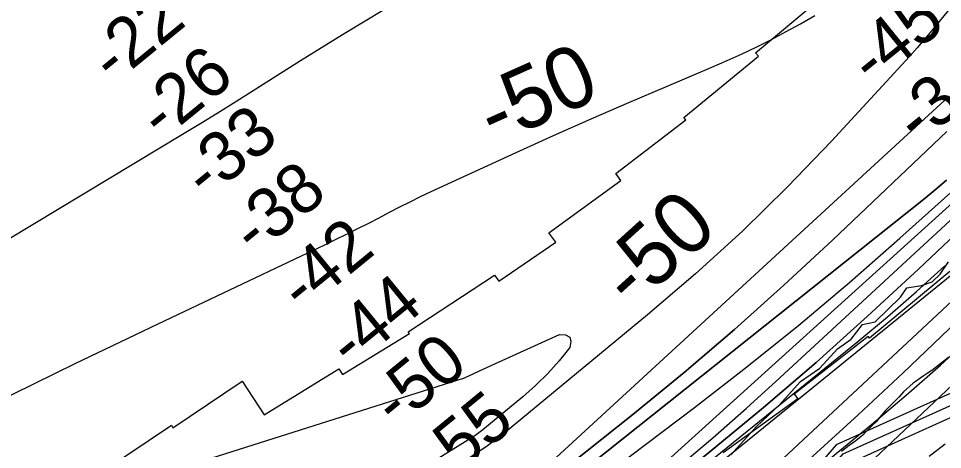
# Model space of a CAD drawing. Extents: x 3208593 to 3246461, y 812903 to 838290.
# Drawn here: x 3213280 to 3214527, y 829398 to 829979 of the extents above; entities that cross this region are included whole.
import ezdxf

# ---------------------------------------------------------------- set-up
doc = ezdxf.new("R2010")
doc.units = 0
for name, color, linetype in [('V-RIVR-EDGE', 7, 'Continuous'), ('V-RIVR-RANG', 7, 'Continuous'), ('V-ROAD-CNTR', 7, 'Continuous'), ('V-RRAP-RVMT', 7, 'Continuous'), ('V-SITE-VEGE', 7, 'Continuous'), ('V-TOPO-DPTH', 7, 'Continuous'), ('V-TOPO-MAJR', 7, 'Continuous'), ('V-TOPO-MAJR-IDEN', 7, 'Continuous'), ('V-TOPO-MINR', 7, 'Continuous'), ('V-TOPO-WATR', 7, 'Continuous')]:
    doc.layers.add(name, color=color, linetype=linetype)

msp = doc.modelspace()

# ---------------------------------------------------------------- linework, layer by layer
at = {"layer": 'V-RIVR-EDGE'}
msp.add_lwpolyline([(3214241.3, 829390.9), (3214276.1, 829428.7), (3214306.6, 829457.7), (3214335.4, 829489.4), (3214361.5, 829507.6), (3214385.5, 829533.6), (3214403.8, 829546.6), (3214419, 829566.5), (3214436, 829570), (3214470.4, 829603.4), (3214478.7, 829615.9), (3214498.7, 829618.9), (3214513.1, 829624.1), (3214524, 829634.1), (3214535.3, 829651)], dxfattribs=at)
at = {"layer": 'V-ROAD-CNTR'}
for points in [[(3212784, 828348.9), (3213009.9, 828462.9), (3213347.7, 828626.5), (3213606.3, 828811.3), (3213843.8, 828911.5), (3214091.9, 829054.1), (3214266.1, 829244.1), (3214392.8, 829391.9), (3214603.9, 829486.9), (3214720, 829566), (3214888.9, 829798.3), (3215094.8, 830091.2), (3215195, 830220.5), (3215374.5, 830389.5), (3215564.5, 830526.7), (3215728.1, 830700.9), (3215823.2, 830758.9), (3216097.6, 830838.1), (3216319.3, 830914.6)], [(3216324, 830900.4), (3216102.1, 830823.8), (3215829.2, 830745.1), (3215737.7, 830689.1), (3215574.5, 830515.4), (3215384.1, 830377.9), (3215206.2, 830210.4), (3215106.8, 830082.3), (3214901.1, 829789.6), (3214730.6, 829555.1), (3214611.2, 829473.7), (3214402, 829379.6), (3214277.3, 829234.1), (3214101.4, 829042.2), (3213850.5, 828898.1), (3213613.7, 828798.1), (3213355.3, 828613.6), (3213016.5, 828449.5), (3212783.7, 828331.9)], [(3214954.5, 829917.7), (3214876.7, 829807), (3214709.4, 829577), (3214596.5, 829500), (3214383.5, 829404.2), (3214254.8, 829254), (3214082.4, 829065.9), (3213837.1, 828925), (3213598.9, 828824.4), (3213340, 828639.5), (3213003.2, 828476.3), (3212784.3, 828365.8)]]:
    msp.add_lwpolyline(points, dxfattribs=at)
at = {"layer": 'V-RRAP-RVMT'}
for p, q in [((3214274.7, 829932.9), (3214365.8, 830008.8)), ((3214177.9, 829845.3), (3214278.6, 829928.2)), ((3214278.6, 829928.2), (3214274.7, 829932.9)), ((3214086.2, 829769.8), (3214180.6, 829842.3)), ((3214180.6, 829842.3), (3214177.9, 829845.3)), ((3213995.8, 829690.2), (3214093, 829760.6)), ((3214093, 829760.6), (3214086.2, 829769.8)), ((3214005.2, 829677.3), (3213995.8, 829690.2)), ((3213928.6, 829624.7), (3214005.2, 829677.3)), ((3214537, 829638.1), (3214428.7, 829548.1)), ((3213805.9, 829556.4), (3213922.7, 829632.9)), ((3213922.7, 829632.9), (3213928.6, 829624.7)), ((3213717.5, 829499.1), (3213807.7, 829554.1)), ((3213807.7, 829554.1), (3213805.9, 829556.4)), ((3214426.8, 829550.4), (3214327, 829472.3)), ((3214428.7, 829548.1), (3214426.8, 829550.4)), ((3213611.7, 829444.5), (3213712.6, 829506.8)), ((3213712.6, 829506.8), (3213717.5, 829499.1)), ((3213488.5, 829427.3), (3213581.9, 829490)), ((3213581.9, 829490), (3213611.7, 829444.5)), ((3214331.7, 829466.4), (3214231.1, 829393.5)), ((3214327, 829472.3), (3214331.7, 829466.4)), ((3213390.7, 829366.4), (3213486.5, 829430.5)), ((3213486.5, 829430.5), (3213488.5, 829427.3))]:
    msp.add_line(p, q, dxfattribs=at)
at = {"layer": 'V-SITE-VEGE'}
for p, q in [((3214523.1, 829512.3), (3214519.1, 829509.5)), ((3214534.9, 829521.9), (3214523.1, 829512.3)), ((3214506.2, 829500.5), (3214501, 829496.9)), ((3214513.8, 829505.5), (3214506.2, 829500.5)), ((3214519.1, 829509.5), (3214513.8, 829505.5)), ((3214487.6, 829487.1), (3214474.2, 829475.6)), ((3214490.2, 829489.1), (3214487.6, 829487.1)), ((3214497.8, 829494.5), (3214490.2, 829489.1)), ((3214501, 829496.9), (3214497.8, 829494.5)), ((3214474.2, 829475.6), (3214468.5, 829468.8)), ((3214468.5, 829468.8), (3214453.1, 829453.4)), ((3214450.3, 829450.4), (3214445.1, 829444.4)), ((3214453.1, 829453.4), (3214450.3, 829450.4)), ((3214437.6, 829435.4), (3214433.2, 829431.2)), ((3214442.3, 829441.4), (3214437.6, 829435.4)), ((3214445.1, 829444.4), (3214442.3, 829441.4)), ((3214426, 829423.8), (3214423.2, 829421.2)), ((3214433.2, 829431.2), (3214426, 829423.8)), ((3214415.2, 829413.4), (3214410, 829409.6)), ((3214419.4, 829417), (3214415.2, 829413.4)), ((3214423.2, 829421.2), (3214419.4, 829417)), ((3214400.9, 829403.3), (3214390.7, 829395.1)), ((3214410, 829409.6), (3214400.9, 829403.3)), ((3214509.2, 829388.9), (3214530.6, 829405.5))]:
    msp.add_line(p, q, dxfattribs=at)
at = {"layer": 'V-TOPO-DPTH'}
for points in [[(3212788.6, 829619.4), (3212788.2, 829398.7), (3212853, 829435.2), (3212924.1, 829476.5), (3212995, 829518.4), (3213504, 829824.3), (3213526.1, 829837.7), (3213548.2, 829851.2), (3213570.1, 829864.9), (3213592, 829878.6), (3213660.8, 829922.3), (3213717.3, 829957.4), (3213774.3, 829991.8)], [(3212788.2, 829398.7), (3212853, 829435.2), (3212924.1, 829476.5), (3212995, 829518.4), (3213504, 829824.3), (3213526.1, 829837.7), (3213548.2, 829851.2), (3213570.1, 829864.9), (3213592, 829878.6), (3213660.8, 829922.3), (3213717.3, 829957.4), (3213774.3, 829991.8)], [(3214535.8, 829874.5), (3213994.4, 829376.8), (3213988.6, 829371.6), (3213982.8, 829366.4), (3213976.8, 829361.4), (3213970.7, 829356.5), (3213959.8, 829347.8), (3213959.2, 829347.2), (3213957.8, 829346.3), (3213957.1, 829345.8), (3213945.8, 829339), (3213939.4, 829335.2), (3213933, 829331.4), (3213926.5, 829327.8), (3213920, 829324.3), (3213904, 829315.8), (3213889.5, 829308), (3213875, 829300.3), (3213860.4, 829292.5), (3213845.9, 829284.7), (3213307, 828996.7), (3213230.6, 828955.6)], [(3214535.8, 829874.5), (3213994.4, 829376.8), (3213988.6, 829371.6), (3213982.8, 829366.4), (3213976.8, 829361.4), (3213970.7, 829356.5), (3213959.8, 829347.8), (3213959.2, 829347.2), (3213957.8, 829346.3), (3213957.1, 829345.8), (3213945.8, 829339), (3213939.4, 829335.2), (3213933, 829331.4), (3213926.5, 829327.8), (3213920, 829324.3), (3213904, 829315.8), (3213889.5, 829308), (3213875, 829300.3), (3213860.4, 829292.5), (3213845.9, 829284.7), (3213307, 828996.7), (3213230.6, 828955.6)], [(3214532.8, 829826.7), (3214378.7, 829680.1), (3214313.1, 829619.3), (3214246.5, 829559.6), (3214178.3, 829501.8), (3214109.2, 829445.1), (3213983.9, 829345.2), (3213976.5, 829339.5), (3213968.9, 829334), (3213961.2, 829328.7), (3213953.3, 829323.7), (3213828.4, 829247.8), (3213757.6, 829205.5), (3213686.4, 829164), (3213614.6, 829123.7), (3213542.3, 829084), (3213000.4, 828792.6)], [(3213000.4, 828792.6), (3213542.3, 829084), (3213614.6, 829123.7), (3213686.4, 829164), (3213757.6, 829205.5), (3213828.4, 829247.8), (3213953.3, 829323.7), (3213961.2, 829328.7), (3213968.9, 829334), (3213976.5, 829339.5), (3213983.9, 829345.2), (3214109.2, 829445.1), (3214178.3, 829501.8), (3214246.5, 829559.6), (3214313.1, 829619.3), (3214378.7, 829680.1), (3214532.8, 829826.7)], [(3213207.6, 828830.7), (3213285.5, 828872.8), (3213363.5, 828914.6), (3213837, 829166.3), (3213860, 829178.5), (3213883, 829190.7), (3213906, 829202.8), (3213929.1, 829215), (3213950.6, 829226.3), (3213962.9, 829232.9), (3213975, 829239.6), (3213987, 829246.4), (3213999, 829253.5), (3214019.8, 829265.9), (3214021.2, 829266.9), (3214022.7, 829267.8), (3214025.5, 829269.9), (3214047.1, 829287.3), (3214059.3, 829297.2), (3214071.3, 829307.3), (3214083.1, 829317.5), (3214094.8, 829327.9), (3214597.3, 829781.5)], [(3213207.6, 828830.7), (3213285.5, 828872.8), (3213363.5, 828914.6), (3213837, 829166.3), (3213860, 829178.5), (3213883, 829190.7), (3213906, 829202.8), (3213929.1, 829215), (3213950.6, 829226.3), (3213962.9, 829232.9), (3213975, 829239.6), (3213987, 829246.4), (3213999, 829253.5), (3214019.8, 829265.9), (3214021.2, 829266.9), (3214022.7, 829267.8), (3214025.5, 829269.9), (3214047.1, 829287.3), (3214059.3, 829297.2), (3214071.3, 829307.3), (3214083.1, 829317.5), (3214094.8, 829327.9), (3214597.3, 829781.5)], [(3214532.6, 829761), (3214517.2, 829747.8), (3214501.5, 829734.8), (3214008.1, 829342.5), (3213993.9, 829331.7), (3213979.4, 829321.2), (3213964.5, 829311.2), (3213949.4, 829301.6), (3213712.7, 829157.8), (3213578.6, 829077.4), (3213443.9, 828997.9), (3213308.3, 828920), (3213172.1, 828843.1), (3212938, 828712.6), (3212911.6, 828697.6), (3212885.3, 828682.3), (3212859.2, 828666.7), (3212833.3, 828650.7), (3212786.7, 828621.7)], [(3212786.8, 828670.8), (3212786.7, 828621.7), (3212833.3, 828650.7), (3212859.2, 828666.7), (3212885.3, 828682.3), (3212911.6, 828697.6), (3212938, 828712.6), (3213172.1, 828843.1), (3213308.3, 828920), (3213443.9, 828997.9), (3213578.6, 829077.4), (3213712.7, 829157.8), (3213949.4, 829301.6), (3213964.5, 829311.2), (3213979.4, 829321.2), (3213993.9, 829331.7), (3214008.1, 829342.5), (3214501.5, 829734.8), (3214517.2, 829747.8), (3214532.6, 829761)], [(3214594.5, 829735.5), (3214494.5, 829640.9), (3214426, 829577.5), (3214356.5, 829515.3), (3214285.5, 829454.7), (3214213.6, 829395.2), (3214054.7, 829266.9), (3214045.1, 829259.5), (3214035.3, 829252.3), (3214025.3, 829245.6), (3214015.1, 829239.2), (3213870.5, 829152.5), (3213787.4, 829103.7), (3213703.8, 829055.9), (3213619.4, 829009.5), (3213534.4, 828964.2), (3213163.5, 828770.4)], [(3214594.5, 829735.5), (3214494.5, 829640.9), (3214426, 829577.5), (3214356.5, 829515.3), (3214285.5, 829454.7), (3214213.6, 829395.2), (3214054.7, 829266.9), (3214045.1, 829259.5), (3214035.3, 829252.3), (3214025.3, 829245.6), (3214015.1, 829239.2), (3213870.5, 829152.5), (3213787.4, 829103.7), (3213703.8, 829055.9), (3213619.4, 829009.5), (3213534.4, 828964.2), (3213163.5, 828770.4)], [(3212786.6, 828551.6), (3212786.4, 828493.6), (3212889, 828559.9), (3212912.2, 828574.5), (3212935.5, 828588.9), (3212959.2, 828602.8), (3212983.1, 828616.4), (3213186.2, 828729.4), (3213311.4, 828799.8), (3213436.2, 828871.1), (3213560.2, 828943.5), (3213683.8, 829016.8), (3214010.4, 829212.5), (3214029.4, 829224.4), (3214048, 829236.9), (3214066.1, 829250.1), (3214083.8, 829263.9), (3214604.5, 829686.5)]]:
    msp.add_lwpolyline(points, dxfattribs=at)
at = {"layer": 'V-TOPO-MAJR'}
for points in [[(3214568.4, 830031.2), (3214512.7, 829963), (3214502.8, 829951.2), (3214492.8, 829939.5), (3214482.6, 829927.9), (3214472.3, 829916.5), (3214377.1, 829813.6), (3214317.9, 829752.1), (3214257, 829692.2), (3214193.8, 829634.9), (3214129, 829579.3), (3213937.2, 829421.3), (3213925.2, 829411.9), (3213913, 829402.8), (3213900.4, 829394.2), (3213887.6, 829385.9), (3213675.5, 829256.1), (3213556, 829183.9), (3213435.9, 829112.7), (3213315.1, 829042.8), (3213193.6, 828974), (3212892.6, 828805.6), (3212864.3, 828789.7), (3212836.1, 828773.7)], [(3213245.7, 829459.3), (3213356.9, 829513.9), (3213468.6, 829567.5), (3213662.3, 829659.1), (3213677.4, 829666.3), (3213692.6, 829673.6), (3213707.8, 829680.9), (3213722.9, 829688.2), (3213724.9, 829689.2), (3213739, 829696.2), (3213753, 829703.2), (3213767, 829710.4), (3213780.9, 829717.7), (3213794.8, 829725), (3213808.8, 829732), (3213822.9, 829738.9), (3213837.1, 829745.6), (3213951.8, 829798.2), (3214002.3, 829821.1), (3214052.9, 829843.7), (3214103.7, 829865.8), (3214154.7, 829887.5), (3214215.9, 829913.3), (3214236.3, 829922.2), (3214256.5, 829931.3), (3214276.5, 829941), (3214296.4, 829950.9), (3214316, 829961.3), (3214335.5, 829971.9), (3214354.8, 829982.9)], [(3213191.1, 828669.1), (3213370.4, 828752.9), (3213484.3, 828808.3), (3213596.9, 828866), (3213707.7, 828927.3), (3213817.2, 828990.8), (3214075.5, 829146.2), (3214090.7, 829155.8), (3214105.7, 829165.9), (3214120.2, 829176.6), (3214134.4, 829187.8), (3214431.2, 829431.5), (3214478.1, 829471.1), (3214524.2, 829511.4), (3214569.2, 829553)]]:
    msp.add_lwpolyline(points, dxfattribs=at)
at = {"layer": 'V-TOPO-MINR'}
for points in [[(3212788.2, 829398.7), (3212853, 829435.2), (3212924.1, 829476.5), (3212995, 829518.4), (3213504, 829824.3), (3213526.1, 829837.7), (3213548.2, 829851.2), (3213570.1, 829864.9), (3213592, 829878.6), (3213660.8, 829922.3), (3213717.3, 829957.4), (3213774.3, 829991.8)], [(3214535.8, 829874.5), (3213994.4, 829376.8), (3213988.6, 829371.6), (3213982.8, 829366.4), (3213976.8, 829361.4), (3213970.7, 829356.5), (3213959.8, 829347.8), (3213959.2, 829347.2), (3213957.8, 829346.3), (3213957.1, 829345.8), (3213945.8, 829339), (3213939.4, 829335.2), (3213933, 829331.4), (3213926.5, 829327.8), (3213920, 829324.3), (3213904, 829315.8), (3213889.5, 829308), (3213875, 829300.3), (3213860.4, 829292.5), (3213845.9, 829284.7), (3213307, 828996.7), (3213230.6, 828955.6)], [(3213000.4, 828792.6), (3213542.3, 829084), (3213614.6, 829123.7), (3213686.4, 829164), (3213757.6, 829205.5), (3213828.4, 829247.8), (3213953.3, 829323.7), (3213961.2, 829328.7), (3213968.9, 829334), (3213976.5, 829339.5), (3213983.9, 829345.2), (3214109.2, 829445.1), (3214178.3, 829501.8), (3214246.5, 829559.6), (3214313.1, 829619.3), (3214378.7, 829680.1), (3214532.8, 829826.7)], [(3212786.7, 828605.6), (3212851.2, 828646), (3212871.3, 828658.4), (3212891.6, 828670.5), (3212912.1, 828682.4), (3212932.6, 828694.1), (3213108.5, 828792), (3213216.9, 828852.9), (3213325, 828914.2), (3213432.7, 828976.2), (3213540.1, 829038.8), (3213944.4, 829275.8), (3213968.4, 829290.4), (3213992.1, 829305.6), (3214015.3, 829321.7), (3214038, 829338.2), (3214192.2, 829454.6), (3214263.2, 829509.5), (3214333.3, 829565.7), (3214401.8, 829623.6), (3214469.5, 829682.7), (3214598.7, 829798.4)], [(3213207.6, 828830.7), (3213285.5, 828872.8), (3213363.5, 828914.6), (3213837, 829166.3), (3213860, 829178.5), (3213883, 829190.7), (3213906, 829202.8), (3213929.1, 829215), (3213950.6, 829226.3), (3213962.9, 829232.9), (3213975, 829239.6), (3213987, 829246.4), (3213999, 829253.5), (3214019.8, 829265.9), (3214021.2, 829266.9), (3214022.7, 829267.8), (3214025.5, 829269.9), (3214047.1, 829287.3), (3214059.3, 829297.2), (3214071.3, 829307.3), (3214083.1, 829317.5), (3214094.8, 829327.9), (3214597.3, 829781.5)], [(3212786.7, 828621.7), (3212833.3, 828650.7), (3212859.2, 828666.7), (3212885.3, 828682.3), (3212911.6, 828697.6), (3212938, 828712.6), (3213172.1, 828843.1), (3213308.3, 828920), (3213443.9, 828997.9), (3213578.6, 829077.4), (3213712.7, 829157.8), (3213949.4, 829301.6), (3213964.5, 829311.2), (3213979.4, 829321.2), (3213993.9, 829331.7), (3214008.1, 829342.5), (3214501.5, 829734.8), (3214517.2, 829747.8), (3214532.6, 829761)], [(3213183.4, 828800.2), (3213306.6, 828865.6), (3213395.4, 828912.6), (3213484.2, 828959.5), (3213573.2, 829006.3), (3213662.2, 829053), (3213742.6, 829095.2), (3213791.1, 829121.1), (3213839.4, 829147.7), (3213887.2, 829175.1), (3213934.7, 829203), (3214017.4, 829252.6), (3214023.3, 829256.2), (3214029, 829260.1), (3214034.6, 829264.1), (3214040.1, 829268.4), (3214123.9, 829335.9), (3214170.8, 829374.4), (3214217.1, 829413.6), (3214262.7, 829453.7), (3214307.7, 829494.5), (3214595.9, 829760.5)], [(3214218.5, 829298.4), (3214660.8, 829710.8)], [(3212786.4, 828493.6), (3212889, 828559.9), (3212912.2, 828574.5), (3212935.5, 828588.9), (3212959.2, 828602.8), (3212983.1, 828616.4), (3213186.2, 828729.4), (3213311.4, 828799.8), (3213436.2, 828871.1), (3213560.2, 828943.5), (3213683.8, 829016.8), (3214010.4, 829212.5), (3214029.4, 829224.4), (3214048, 829236.9), (3214066.1, 829250.1), (3214083.8, 829263.9), (3214604.5, 829686.5)], [(3213230.3, 828715.5), (3213287.2, 828744.6), (3213320.4, 828761.3), (3213394.2, 828798.2), (3213468.1, 828834.9), (3213542.2, 828871.2), (3213616.4, 828907.3), (3213632.4, 828915.1), (3213711.9, 828954.9), (3213790.6, 828996.2), (3213868.2, 829039.5), (3213945, 829084.3), (3214078.7, 829164.8), (3214087.9, 829170.6), (3214096.9, 829176.6), (3214105.7, 829183.1), (3214114.2, 829189.8), (3214225.7, 829281.2), (3214289.3, 829334.5), (3214352, 829388.7), (3214413.4, 829444.4), (3214474, 829501.1), (3214658.8, 829678)], [(3212786.5, 828511.6), (3212869, 828565), (3212898.6, 828583.7), (3212928.5, 828602.1), (3212958.7, 828619.9), (3212989.2, 828637.2), (3213330.5, 828827.2), (3213450.3, 828894.6), (3213569.7, 828962.8), (3213688.3, 829032.1), (3213806.6, 829102.2), (3214012.7, 829225.8), (3214027.3, 829235), (3214041.7, 829244.6), (3214055.6, 829254.8), (3214069.2, 829265.4), (3214412.8, 829543.5), (3214452.7, 829576.7), (3214492, 829610.7), (3214530.3, 829645.7)], [(3214345.9, 829301.1), (3214678.7, 829615.4)], [(3213412.6, 829345.9), (3213882.1, 829494.5), (3213914.1, 829509.5), (3214010.1, 829552.9), (3214018.4, 829552.3), (3214024, 829549.5), (3214025.4, 829543.5), (3214024.2, 829535.2), (3214009.6, 829517.4), (3213994.3, 829500.3), (3213977.9, 829484.3), (3213960.7, 829469.1), (3213906.9, 829424.4), (3213903.4, 829421.6), (3213899.8, 829418.9), (3213896.1, 829416.4), (3213892.4, 829414), (3213826.1, 829373.1)]]:
    msp.add_lwpolyline(points, dxfattribs=at)
at = {"layer": 'V-TOPO-WATR'}
msp.add_lwpolyline([(3213163.5, 828770.4), (3213534.4, 828964.2), (3213619.4, 829009.5), (3213703.8, 829055.9), (3213787.4, 829103.7), (3213870.5, 829152.5), (3214015.1, 829239.2), (3214025.3, 829245.6), (3214035.3, 829252.3), (3214045.1, 829259.5), (3214054.7, 829266.9), (3214213.6, 829395.2), (3214285.5, 829454.7), (3214356.5, 829515.3), (3214426, 829577.5), (3214494.5, 829640.9), (3214594.5, 829735.5)], dxfattribs=at)

# ---------------------------------------------------------------- texts
at = {"layer": 'V-RIVR-RANG'}
for s, rotation, p in [('-22', 39.2982, (3213408.7, 829889.4)), ('-45', 39.0478, (3214432.9, 829886.7)), ('-26', 39.2982, (3213473.9, 829813.5)), ('-34', 39.0478, (3214494.2, 829807.7)), ('-33', 39.2982, (3213534.1, 829733.6)), ('-38', 39.2982, (3213599.2, 829657.7)), ('-42', 39.2982, (3213663.6, 829581.1)), ('-44', 39.2982, (3213728.9, 829505.4)), ('-50', 39.2982, (3213789.6, 829425.8)), ('-55', 39.2982, (3213852.1, 829347.7))]:
    msp.add_text(s, height=67, rotation=rotation, dxfattribs=at).set_placement(p)
at = {"layer": 'V-TOPO-MAJR-IDEN'}
for rotation, p in [(24.0303, (3213922.1, 829808.1)), (42.1951, (3214108.1, 829585.2))]:
    msp.add_text('-50', height=83, rotation=rotation, dxfattribs=at).set_placement(p)

doc.saveas('drawing.dxf')
